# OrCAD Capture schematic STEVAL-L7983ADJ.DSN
size A4; title: STEVAL-L7983ADJ; rev: 1.0
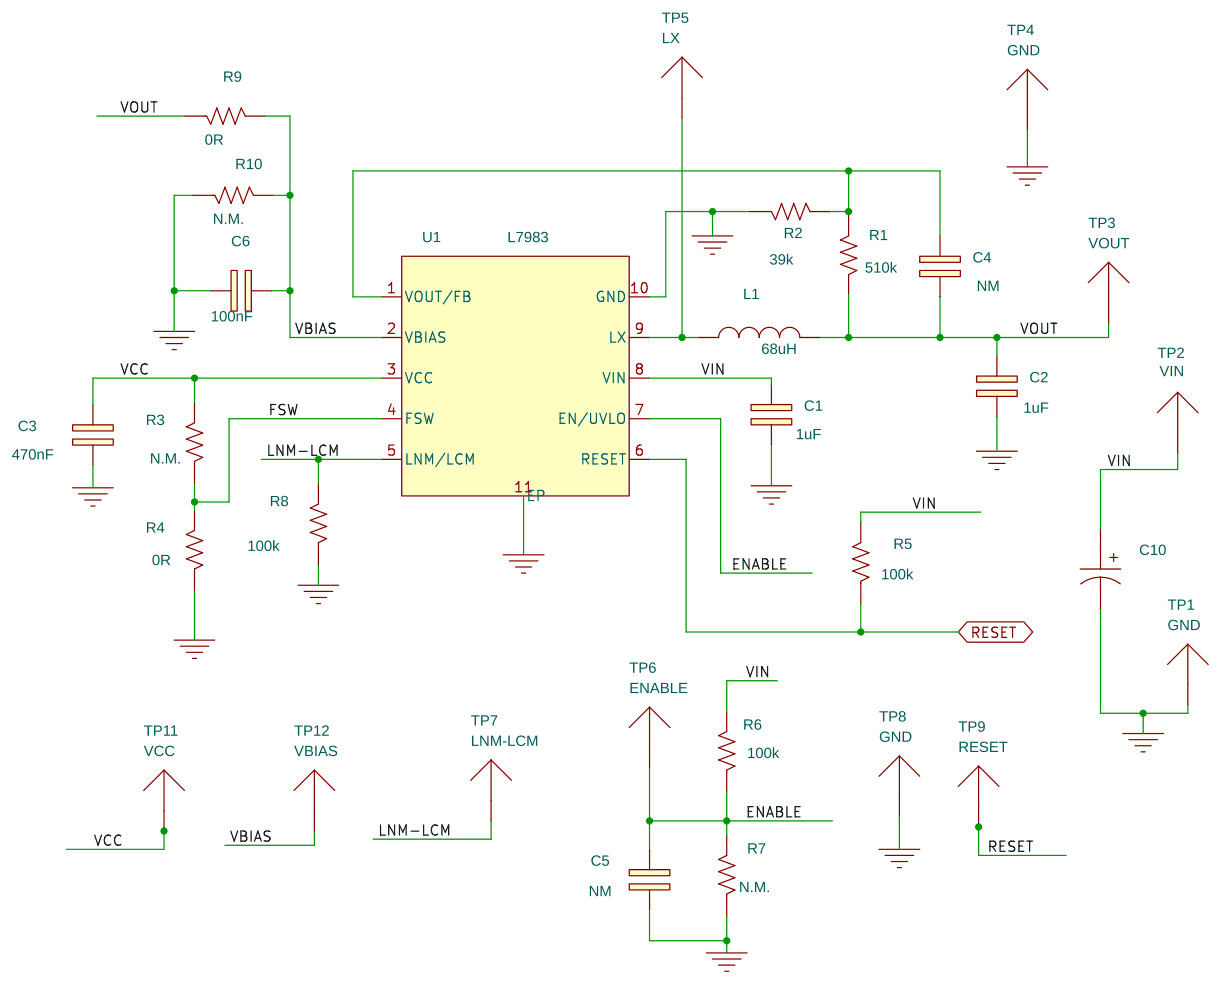
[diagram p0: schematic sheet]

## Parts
C1  1uF  [c0805_1206_t]
C2  1uF  [c0805_1206_t]
C3  470nF  [CAPC-0603]
C4  NM  [CAPC-0603]
C5  NM  [CAPC-0603]
C6  100nF  [CAPC-0603]
C10  Radial 6.3mm-SMD  [CEVSMD_6V3X8_T]
L1  68uH  [Ind_LPS4018_LPS5030]
R1  510k  [RESC-0603]
R2  39k  [RESC-0603]
R3  N.M.  [RESC-0603]
R4  0R  [RESC-0603]
R5  100k  [RESC-0603]
R6  100k  [RESC-0603]
R7  N.M.  [RESC-0603]
R8  100k  [RESC-0603]
R9  0R  [RESC-0603]
R10  N.M.  [RESC-0603]
TP1  GND  [STRIP1]
TP2  VIN  [STRIP1]
TP3  VOUT  [STRIP1]
TP4  GND  [STRIP1]
TP5  LX  [STRIP1]
TP6  ENABLE  [STRIP1]
TP7  LNM-LCM  [STRIP1]
TP8  GND  [STRIP1]
TP9  RESET  [STRIP1]
TP11  VCC  [STRIP1]
TP12  VBIAS  [STRIP1]
U1  L7983  [dfn3x3_L7983]

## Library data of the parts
C1 = CNP_2: Type: 100V
C2 = CNP_2: Type: 16V
C3-C6 = CNP_2: Type: 50V
C10 = CAP_Radial_6.3mm-SMD
L1 = INDC-COILCRAFT-MSS1246
R1-R10 = R
TP1-TP9 TP11 TP12 = TP_0.9mm
U1 = L7983_DFN10_3x3

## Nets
GND: C1.2 C2.2 C3.1 C5.1 C6.1 C10.N R2.1 R4.1 R7.1 R8.1 R10.1 TP1.1 TP4.1 TP8.1 U1.10(GND) U1.11(EP)
VCC: C3.2 R3.2 TP11.1 U1.3(VCC)
VIN: C1.1 C10.P R5.2 R6.2 TP2.1 U1.8(VIN)
ENABLE: C5.2 R6.1 R7.2 TP6.1 U1.7(EN/UVLO)
FSW: R3.1 R4.2 U1.4(FSW)
LNM-LCM: R8.2 TP7.1 U1.5(LNM/LCM)
RESET: R5.1 TP9.1 U1.6(RESET)
VBIAS: C6.2 R9.2 R10.2 TP12.1 U1.2(VBIAS)
VOUT: C2.1 C4.1 L1.2 R1.2 R9.1 TP3.1
N3652199: L1.1 TP5.1 U1.9(LX)
N3652645: C4.2 R1.1 R2.2 U1.1(VOUT/FB)
